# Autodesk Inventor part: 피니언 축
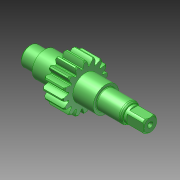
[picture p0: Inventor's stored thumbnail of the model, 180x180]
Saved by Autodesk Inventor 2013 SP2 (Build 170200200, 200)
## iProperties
Created: 2024-11
Part Number: 피니언 축
Material: Generic
Document SubType Name: Modeling
Designer: a
Density: 1 g/cm^3
Author: a
변환 표준: STEP AP214IS
전처리기: Build: 200, Release: 2013 SP2 Update 6 - Date: Thu 07/17/2014
전송 단위: 밀리미터
불확실성: 0.01
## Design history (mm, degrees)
node "피니언 축1"
node "솔리드1"
node "기준1"
